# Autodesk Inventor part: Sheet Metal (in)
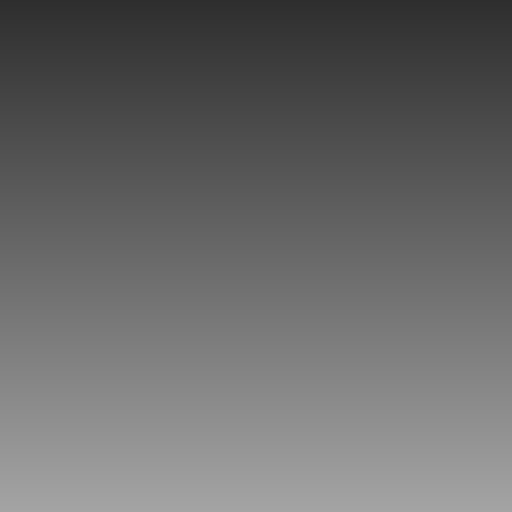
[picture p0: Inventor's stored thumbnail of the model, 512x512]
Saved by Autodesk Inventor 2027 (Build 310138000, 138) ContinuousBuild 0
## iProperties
Shininess: 64.0
Length Units: 11272
Angle Units: 11279
Time Units: 11290
Mass Units: 11286
Length Display Precision: 3
Angle Display Precision: 2
Compacted: True
Part Number: Sheet Metal (in)
Document SubType Name: Sheet Metal
Created: 2002-07
Material: Generic
Density: 1 g/cm^3
Sheet Metal Rule: Default
Appearance: Default
Density: 0.0
Volumn: 0.0
Area: 0.0
PropertySet Name: Model Information
Control State: 0
Master: False
Checked Out: False
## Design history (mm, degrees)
other parameters: "Thickness" = 3.048, "BendRadius" = 3.048 (= Thickness), "BendReliefWidth" = 3.048 (= Thickness), "BendReliefDepth" = 1.524 (= 0.5 x Thickness), "CornerReliefSize" = 12.192 (= 4 x Thickness), "SeamGap" = 0.00508, "MinimumRemnant" = 6.096 (= 2 x Thickness), "TransitionRadius" = 3.048 (= BendRadius), "JacobiRadiusSize" = 3.048 (= BendRadius), "GapSize" = 3.048 (= Thickness)
